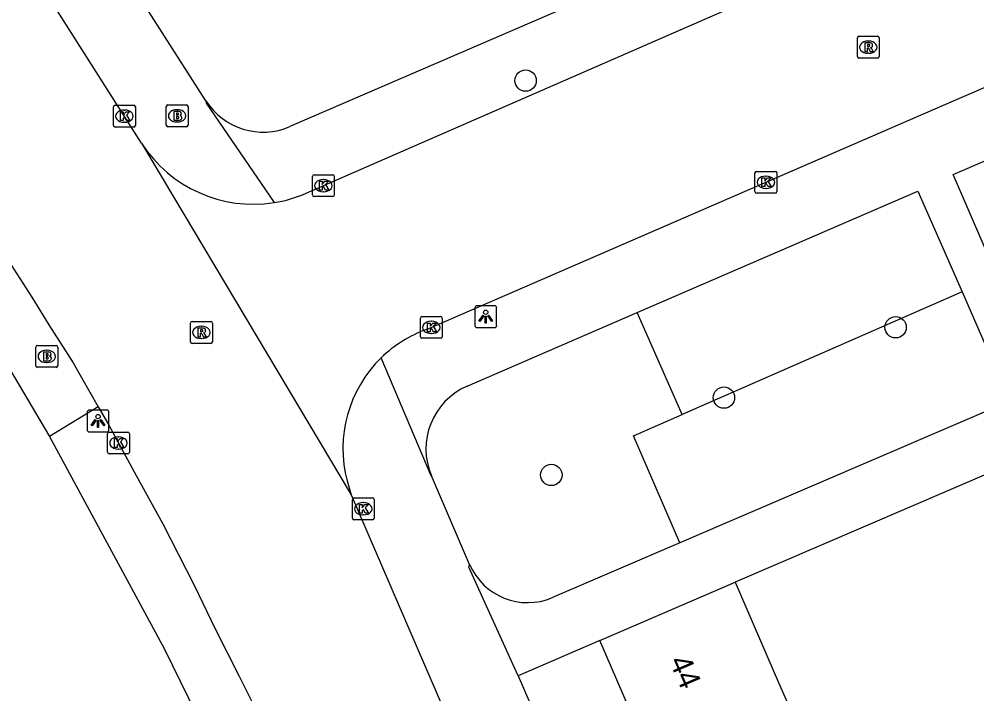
# Model space of a CAD drawing. Extents: x 159353 to 160616, y 385893 to 387321.
# Drawn here: x 159510 to 159553.81, y 386356.35 to 386387.21 of the extents above; entities that cross this region are included whole.
import ezdxf

# ---------------------------------------------------------------- set-up
doc = ezdxf.new("R2010")
doc.units = 0
for name, color, linetype in [('IMGEO_Boom', 7, 'Continuous'), ('IMGEO_Brandkraan', 7, 'Continuous'), ('IMGEO_Groenvoorziening', 7, 'Continuous'), ('IMGEO_Kolk', 7, 'Continuous'), ('IMGEO_Lichtpunt', 7, 'Continuous'), ('IMGEO_Muur', 7, 'Continuous'), ('IMGEO_Pand', 7, 'Continuous'), ('IMGEO_Pand_nummerreeks', 7, 'Continuous'), ('IMGEO_Rijbaan_lokaal_gesloten', 7, 'Continuous'), ('IMGEO_Rioolput', 7, 'Continuous'), ('IMGEO_Voetpad_open', 7, 'Continuous')]:
    doc.layers.add(name, color=color, linetype=linetype)

msp = doc.modelspace()

# ---------------------------------------------------------------- linework, layer by layer
at = {"layer": 'IMGEO_Boom'}
for centre in [(159533.167, 386384.407), (159550.091, 386373.12), (159542.239, 386369.903), (159534.343, 386366.368)]:
    msp.add_circle(centre, 0.489, dxfattribs=at)
at = {"layer": 'IMGEO_Brandkraan'}
for p, q in [((159516.802, 386383.292), (159517.654, 386383.292)), ((159516.727, 386382.366), (159516.727, 386383.218)), ((159517.215, 386383.072), (159517.24, 386383.072)), ((159517.728, 386383.218), (159517.728, 386382.366)), ((159517.238, 386382.512), (159517.213, 386382.512)), ((159517.654, 386382.292), (159516.802, 386382.292)), ((159510.839, 386372.289), (159511.691, 386372.289)), ((159510.764, 386371.363), (159510.764, 386372.215)), ((159511.252, 386372.069), (159511.277, 386372.069)), ((159511.765, 386372.215), (159511.765, 386371.363)), ((159511.275, 386371.509), (159511.25, 386371.509)), ((159511.691, 386371.289), (159510.839, 386371.289))]:
    msp.add_line(p, q, dxfattribs=at)
for points in [[(159516.802, 386383.292), (159517.654, 386383.292)], [(159516.727, 386382.366), (159516.727, 386383.218)], [(159517.075, 386382.992), (159517.075, 386382.592), (159517.288, 386382.592)], [(159517.306, 386382.992), (159517.075, 386382.992)], [(159517.254, 386382.911), (159517.2, 386382.911), (159517.2, 386382.835)], [(159517.2, 386382.835), (159517.253, 386382.835)], [(159517.728, 386383.218), (159517.728, 386382.366)], [(159517.262, 386382.759), (159517.2, 386382.759), (159517.2, 386382.678)], [(159517.2, 386382.678), (159517.262, 386382.678)], [(159517.654, 386382.292), (159516.802, 386382.292)], [(159510.839, 386372.289), (159511.691, 386372.289)], [(159510.764, 386371.363), (159510.764, 386372.215)], [(159511.112, 386371.989), (159511.112, 386371.589), (159511.325, 386371.589)], [(159511.343, 386371.989), (159511.112, 386371.989)], [(159511.291, 386371.908), (159511.237, 386371.908), (159511.237, 386371.832)], [(159511.765, 386372.215), (159511.765, 386371.363)], [(159511.237, 386371.832), (159511.29, 386371.832)], [(159511.299, 386371.756), (159511.237, 386371.756), (159511.237, 386371.675)], [(159511.237, 386371.675), (159511.299, 386371.675)], [(159511.691, 386371.289), (159510.839, 386371.289)]]:
    msp.add_lwpolyline(points, dxfattribs=at)
for centre, radius, start, end in [((159516.804, 386383.216), 0.0765, 91.552, 178.448), ((159516.804, 386383.216), 0.0765, 91.552, 178.448), ((159517.652, 386383.216), 0.0765, 1.552, 88.448), ((159517.652, 386383.216), 0.0765, 1.552, 88.448), ((159517.255, 386382.873), 0.0379, 267.8285, 90.9355), ((159517.31, 386382.847), 0.145, 59.4692, 91.5367), ((159517.335, 386382.894), 0.0922, 285.5137, 58.1501), ((159517.34, 386382.702), 0.105, 301.3115, 78.989), ((159516.804, 386382.368), 0.0765, 181.552, 268.448), ((159516.804, 386382.368), 0.0765, 181.552, 268.448), ((159517.263, 386382.718), 0.0404, 269.8759, 90.5077), ((159517.294, 386382.843), 0.251, 268.6676, 293.5347), ((159517.652, 386382.368), 0.0765, 271.552, 358.448), ((159517.652, 386382.368), 0.0765, 271.552, 358.448), ((159510.841, 386372.213), 0.0765, 91.552, 178.448), ((159510.841, 386372.213), 0.0765, 91.552, 178.448), ((159511.689, 386372.213), 0.0765, 1.552, 88.448), ((159511.689, 386372.213), 0.0765, 1.552, 88.448), ((159511.292, 386371.87), 0.0379, 267.8285, 90.9355), ((159511.347, 386371.844), 0.145, 59.4692, 91.5367), ((159511.372, 386371.891), 0.0922, 285.5137, 58.1501), ((159511.3, 386371.715), 0.0404, 269.8759, 90.5077), ((159511.331, 386371.84), 0.251, 268.6676, 293.5347), ((159511.377, 386371.699), 0.105, 301.3115, 78.989), ((159510.841, 386371.365), 0.0765, 181.552, 268.448), ((159510.841, 386371.365), 0.0765, 181.552, 268.448), ((159511.689, 386371.365), 0.0765, 271.552, 358.448), ((159511.689, 386371.365), 0.0765, 271.552, 358.448)]:
    msp.add_arc(centre, radius, start, end, dxfattribs=at)
for centre, major_axis, ratio, start_param, end_param in [((159517.214, 386382.792), (-0.387, 0.002), 0.722429, 4.712389, 7.853982), ((159517.239, 386382.792), (-0.39, 0.002), 0.717154, 1.570796, 4.712389), ((159511.251, 386371.789), (-0.387, 0.002), 0.722429, 4.712389, 7.853982), ((159511.276, 386371.789), (-0.39, 0.002), 0.717154, 1.570796, 4.712389)]:
    msp.add_ellipse(centre, major_axis=major_axis, ratio=ratio, start_param=start_param, end_param=end_param, dxfattribs=at)
at = {"layer": 'IMGEO_Groenvoorziening'}
for points in [[(159553.129, 386374.738), (159540.323, 386369.126)], [(159540.323, 386369.126), (159538.273, 386373.794)], [(159540.228, 386363.264), (159538.097, 386368.15), (159540.323, 386369.126)]]:
    msp.add_lwpolyline(points, dxfattribs=at)
at = {"layer": 'IMGEO_Kolk'}
for p, q in [((159514.39, 386383.277), (159515.242, 386383.277)), ((159514.315, 386382.351), (159514.315, 386383.203)), ((159514.803, 386383.057), (159514.828, 386383.057)), ((159515.316, 386383.203), (159515.316, 386382.351)), ((159514.826, 386382.497), (159514.801, 386382.497)), ((159515.242, 386382.277), (159514.39, 386382.277)), ((159543.659, 386379.327), (159543.659, 386380.179)), ((159543.734, 386380.253), (159544.586, 386380.253)), ((159544.66, 386380.179), (159544.66, 386379.327)), ((159523.417, 386379.173), (159523.417, 386380.025)), ((159523.492, 386380.099), (159524.344, 386380.099)), ((159523.905, 386379.879), (159523.93, 386379.879)), ((159524.418, 386380.025), (159524.418, 386379.173)), ((159544.147, 386380.033), (159544.172, 386380.033)), ((159523.928, 386379.319), (159523.903, 386379.319)), ((159544.17, 386379.473), (159544.145, 386379.473)), ((159524.344, 386379.099), (159523.492, 386379.099)), ((159544.586, 386379.253), (159543.734, 386379.253)), ((159528.427, 386373.616), (159529.279, 386373.616)), ((159528.352, 386372.69), (159528.352, 386373.542)), ((159528.84, 386373.396), (159528.865, 386373.396)), ((159529.353, 386373.542), (159529.353, 386372.69)), ((159528.863, 386372.836), (159528.838, 386372.836)), ((159529.279, 386372.616), (159528.427, 386372.616)), ((159514.043, 386367.402), (159514.043, 386368.254)), ((159514.118, 386368.328), (159514.97, 386368.328)), ((159514.531, 386368.108), (159514.556, 386368.108)), ((159515.044, 386368.254), (159515.044, 386367.402)), ((159514.554, 386367.548), (159514.529, 386367.548)), ((159514.97, 386367.328), (159514.118, 386367.328)), ((159525.317, 386365.321), (159526.169, 386365.321)), ((159525.242, 386364.395), (159525.242, 386365.247)), ((159525.73, 386365.101), (159525.755, 386365.101)), ((159526.243, 386365.247), (159526.243, 386364.395)), ((159525.753, 386364.541), (159525.728, 386364.541)), ((159526.169, 386364.321), (159525.317, 386364.321))]:
    msp.add_line(p, q, dxfattribs=at)
for points in [[(159514.39, 386383.277), (159515.242, 386383.277)], [(159514.315, 386382.351), (159514.315, 386383.203)], [(159514.636, 386382.977), (159514.759, 386382.977), (159514.759, 386382.826), (159514.889, 386382.977), (159515.053, 386382.977), (159514.907, 386382.826), (159515.06, 386382.577), (159514.908, 386382.577), (159514.823, 386382.741), (159514.759, 386382.674), (159514.759, 386382.577), (159514.636, 386382.577), (159514.636, 386382.977)], [(159515.316, 386383.203), (159515.316, 386382.351)], [(159515.242, 386382.277), (159514.39, 386382.277)], [(159543.659, 386379.327), (159543.659, 386380.179)], [(159543.734, 386380.253), (159544.586, 386380.253)], [(159544.66, 386380.179), (159544.66, 386379.327)], [(159523.417, 386379.173), (159523.417, 386380.025)], [(159523.492, 386380.099), (159524.344, 386380.099)], [(159523.738, 386379.799), (159523.861, 386379.799), (159523.861, 386379.648), (159523.991, 386379.799), (159524.155, 386379.799), (159524.009, 386379.648), (159524.162, 386379.399), (159524.01, 386379.399), (159523.925, 386379.563), (159523.861, 386379.496), (159523.861, 386379.399), (159523.738, 386379.399), (159523.738, 386379.799)], [(159524.418, 386380.025), (159524.418, 386379.173)], [(159543.98, 386379.953), (159544.103, 386379.953), (159544.103, 386379.802), (159544.233, 386379.953), (159544.397, 386379.953), (159544.251, 386379.802), (159544.404, 386379.553), (159544.252, 386379.553), (159544.167, 386379.717), (159544.103, 386379.65), (159544.103, 386379.553), (159543.98, 386379.553), (159543.98, 386379.953)], [(159524.344, 386379.099), (159523.492, 386379.099)], [(159544.586, 386379.253), (159543.734, 386379.253)], [(159528.427, 386373.616), (159529.279, 386373.616)], [(159528.352, 386372.69), (159528.352, 386373.542)], [(159528.673, 386373.316), (159528.796, 386373.316), (159528.796, 386373.165), (159528.926, 386373.316), (159529.09, 386373.316), (159528.944, 386373.165), (159529.097, 386372.916), (159528.945, 386372.916), (159528.86, 386373.08), (159528.796, 386373.013), (159528.796, 386372.916), (159528.673, 386372.916), (159528.673, 386373.316)], [(159529.353, 386373.542), (159529.353, 386372.69)], [(159529.279, 386372.616), (159528.427, 386372.616)], [(159514.043, 386367.402), (159514.043, 386368.254)], [(159514.118, 386368.328), (159514.97, 386368.328)], [(159514.364, 386368.028), (159514.487, 386368.028), (159514.487, 386367.877), (159514.617, 386368.028), (159514.781, 386368.028), (159514.635, 386367.877), (159514.788, 386367.628), (159514.636, 386367.628), (159514.551, 386367.792), (159514.487, 386367.725), (159514.487, 386367.628), (159514.364, 386367.628), (159514.364, 386368.028)], [(159515.044, 386368.254), (159515.044, 386367.402)], [(159514.97, 386367.328), (159514.118, 386367.328)], [(159525.317, 386365.321), (159526.169, 386365.321)], [(159525.242, 386364.395), (159525.242, 386365.247)], [(159525.563, 386365.021), (159525.686, 386365.021), (159525.686, 386364.87), (159525.816, 386365.021), (159525.98, 386365.021), (159525.834, 386364.87), (159525.987, 386364.621), (159525.835, 386364.621), (159525.75, 386364.785), (159525.686, 386364.718), (159525.686, 386364.621), (159525.563, 386364.621), (159525.563, 386365.021)], [(159526.243, 386365.247), (159526.243, 386364.395)], [(159526.169, 386364.321), (159525.317, 386364.321)]]:
    msp.add_lwpolyline(points, dxfattribs=at)
for centre, start, end in [((159514.392, 386383.201), 91.552, 178.448), ((159514.392, 386383.201), 91.552, 178.448), ((159515.24, 386383.201), 1.552, 88.448), ((159515.24, 386383.201), 1.552, 88.448), ((159514.392, 386382.353), 181.552, 268.448), ((159514.392, 386382.353), 181.552, 268.448), ((159515.24, 386382.353), 271.552, 358.448), ((159515.24, 386382.353), 271.552, 358.448), ((159543.736, 386380.177), 91.552, 178.448), ((159543.736, 386380.177), 91.552, 178.448), ((159544.584, 386380.177), 1.552, 88.448), ((159544.584, 386380.177), 1.552, 88.448), ((159523.494, 386380.023), 91.552, 178.448), ((159523.494, 386380.023), 91.552, 178.448), ((159524.342, 386380.023), 1.552, 88.448), ((159524.342, 386380.023), 1.552, 88.448), ((159543.736, 386379.329), 181.552, 268.448), ((159543.736, 386379.329), 181.552, 268.448), ((159544.584, 386379.329), 271.552, 358.448), ((159544.584, 386379.329), 271.552, 358.448), ((159523.494, 386379.175), 181.552, 268.448), ((159523.494, 386379.175), 181.552, 268.448), ((159524.342, 386379.175), 271.552, 358.448), ((159524.342, 386379.175), 271.552, 358.448), ((159528.429, 386373.54), 91.552, 178.448), ((159528.429, 386373.54), 91.552, 178.448), ((159529.277, 386373.54), 1.552, 88.448), ((159529.277, 386373.54), 1.552, 88.448), ((159528.429, 386372.692), 181.552, 268.448), ((159528.429, 386372.692), 181.552, 268.448), ((159529.277, 386372.692), 271.552, 358.448), ((159529.277, 386372.692), 271.552, 358.448), ((159514.12, 386368.252), 91.552, 178.448), ((159514.12, 386368.252), 91.552, 178.448), ((159514.968, 386368.252), 1.552, 88.448), ((159514.968, 386368.252), 1.552, 88.448), ((159514.12, 386367.404), 181.552, 268.448), ((159514.12, 386367.404), 181.552, 268.448), ((159514.968, 386367.404), 271.552, 358.448), ((159514.968, 386367.404), 271.552, 358.448), ((159525.319, 386365.245), 91.552, 178.448), ((159525.319, 386365.245), 91.552, 178.448), ((159526.167, 386365.245), 1.552, 88.448), ((159526.167, 386365.245), 1.552, 88.448), ((159525.319, 386364.397), 181.552, 268.448), ((159525.319, 386364.397), 181.552, 268.448), ((159526.167, 386364.397), 271.552, 358.448), ((159526.167, 386364.397), 271.552, 358.448)]:
    msp.add_arc(centre, 0.0765, start, end, dxfattribs=at)
for centre, major_axis, ratio, start_param, end_param in [((159514.802, 386382.777), (-0.387, 0.002), 0.722429, 4.712389, 7.853982), ((159514.827, 386382.777), (-0.39, 0.002), 0.717154, 1.570796, 4.712389), ((159523.904, 386379.599), (-0.387, 0.002), 0.722429, 4.712389, 7.853982), ((159523.929, 386379.599), (-0.39, 0.002), 0.717154, 1.570796, 4.712389), ((159544.146, 386379.753), (-0.387, 0.002), 0.722429, 4.712389, 7.853982), ((159544.171, 386379.753), (-0.39, 0.002), 0.717154, 1.570796, 4.712389), ((159528.839, 386373.116), (-0.387, 0.002), 0.722429, 4.712389, 7.853982), ((159528.864, 386373.116), (-0.39, 0.002), 0.717154, 1.570796, 4.712389), ((159514.53, 386367.828), (-0.387, 0.002), 0.722429, 4.712389, 7.853982), ((159514.555, 386367.828), (-0.39, 0.002), 0.717154, 1.570796, 4.712389), ((159525.729, 386364.821), (-0.387, 0.002), 0.722429, 4.712389, 7.853982), ((159525.754, 386364.821), (-0.39, 0.002), 0.717154, 1.570796, 4.712389)]:
    msp.add_ellipse(centre, major_axis=major_axis, ratio=ratio, start_param=start_param, end_param=end_param, dxfattribs=at)
at = {"layer": 'IMGEO_Lichtpunt'}
for p, q in [((159531.749, 386374.103), (159530.941, 386374.103)), ((159531.749, 386374.103), (159530.941, 386374.103)), ((159530.847, 386374.008), (159530.847, 386373.201)), ((159530.847, 386374.008), (159530.847, 386373.201)), ((159531.843, 386373.201), (159531.843, 386374.008)), ((159531.843, 386373.201), (159531.843, 386374.008)), ((159530.941, 386373.107), (159531.749, 386373.107)), ((159530.941, 386373.107), (159531.749, 386373.107)), ((159513.112, 386369.239), (159513.112, 386368.432)), ((159513.112, 386369.239), (159513.112, 386368.432)), ((159514.014, 386369.334), (159513.206, 386369.334)), ((159514.014, 386369.334), (159513.206, 386369.334)), ((159514.108, 386368.432), (159514.108, 386369.239)), ((159514.108, 386368.432), (159514.108, 386369.239)), ((159513.206, 386368.338), (159514.014, 386368.338)), ((159513.206, 386368.338), (159514.014, 386368.338))]:
    msp.add_line(p, q, dxfattribs=at)
for points in [[(159531.221, 386373.672), (159531.26, 386373.644), (159531.072, 386373.382), (159531.034, 386373.409), (159531.221, 386373.672)], [(159531.323, 386373.624), (159531.37, 386373.624), (159531.37, 386373.302), (159531.323, 386373.302), (159531.323, 386373.624)], [(159531.433, 386373.644), (159531.471, 386373.671), (159531.658, 386373.409), (159531.619, 386373.381), (159531.433, 386373.644)], [(159513.486, 386368.903), (159513.525, 386368.875), (159513.337, 386368.613), (159513.299, 386368.64), (159513.486, 386368.903)], [(159513.588, 386368.855), (159513.635, 386368.855), (159513.635, 386368.533), (159513.588, 386368.533), (159513.588, 386368.855)], [(159513.698, 386368.875), (159513.736, 386368.902), (159513.923, 386368.64), (159513.884, 386368.612), (159513.698, 386368.875)]]:
    msp.add_lwpolyline(points, dxfattribs=at)
for centre in [(159531.346, 386373.806), (159513.611, 386369.037)]:
    msp.add_circle(centre, 0.0994, dxfattribs=at)
for centre, start, end in [((159530.941, 386374.008), 90, 180), ((159530.941, 386374.008), 90, 180), ((159531.749, 386374.008), 0, 90), ((159531.749, 386374.008), 0, 90), ((159530.941, 386373.201), 180, 270), ((159530.941, 386373.201), 180, 270), ((159531.749, 386373.201), 270, 0), ((159531.749, 386373.201), 270, 360), ((159513.206, 386369.239), 90, 180), ((159513.206, 386369.239), 90, 180), ((159514.014, 386369.239), 0, 90), ((159514.014, 386369.239), 0, 90), ((159513.206, 386368.432), 180, 270), ((159513.206, 386368.432), 180, 270), ((159514.014, 386368.432), 270, 0), ((159514.014, 386368.432), 270, 360)]:
    msp.add_arc(centre, 0.0946, start, end, dxfattribs=at)
at = {"layer": 'IMGEO_Muur'}
msp.add_lwpolyline([(159556.517, 386367.373), (159542.759, 386361.47)], dxfattribs=at)
at = {"layer": 'IMGEO_Pand'}
for points in [[(159536.57, 386358.8), (159542.759, 386361.47)], [(159542.759, 386361.47), (159544.739, 386356.879), (159545.132, 386355.967)], [(159538.943, 386353.297), (159536.57, 386358.8)]]:
    msp.add_lwpolyline(points, dxfattribs=at)
at = {"layer": 'IMGEO_Rijbaan_lokaal_gesloten'}
for points in [[(159515.604, 386381.536), (159500.36, 386405.492), (159500, 386406.055), (159471.301, 386450.928)], [(159523.135, 386379.256), (159544.96, 386388.795), (159556.875, 386393.929), (159564.458, 386397.238)], [(159528.635, 386373.023), (159553.089, 386383.626), (159573.819, 386392.563)], [(159515.604, 386381.536), (159525.194, 386365.458)], [(159508.049, 386378.563), (159509.479, 386376.213), (159510.58, 386374.496), (159511.352, 386373.226), (159512.473, 386371.498), (159513.621, 386369.485)], [(159513.621, 386369.485), (159514.085, 386368.672), (159515.356, 386366.345), (159516.578, 386364.138), (159518, 386361.321), (159518.981, 386359.293), (159520.063, 386357.166), (159521.044, 386355.208), (159522.497, 386352.051), (159523.869, 386348.954), (159528.006, 386339.414), (159538.567, 386315.088)], [(159525.008, 386366.09), (159525.194, 386365.458)], [(159525.194, 386365.458), (159527.379, 386360.366), (159547.269, 386314.331)]]:
    msp.add_lwpolyline(points, dxfattribs=at)
for centre, radius, start, end in [((159520.708, 386384.815), 6.066, 212.7203, 279.0321), ((159520.707, 386384.812), 6.063, 279.0425, 293.6062), ((159530.607, 386367.573), 5.796, 109.8888, 134.2708), ((159530.607, 386367.577), 5.793, 134.2981, 194.8752)]:
    msp.add_arc(centre, radius, start, end, dxfattribs=at)
at = {"layer": 'IMGEO_Rioolput'}
for p, q in [((159548.342, 386385.506), (159548.342, 386386.358)), ((159548.417, 386386.432), (159549.269, 386386.432)), ((159549.343, 386386.358), (159549.343, 386385.506)), ((159548.83, 386386.212), (159548.855, 386386.212)), ((159549.269, 386385.432), (159548.417, 386385.432)), ((159548.853, 386385.652), (159548.828, 386385.652)), ((159517.837, 386372.46), (159517.837, 386373.312)), ((159517.912, 386373.386), (159518.764, 386373.386)), ((159518.325, 386373.166), (159518.35, 386373.166)), ((159518.838, 386373.312), (159518.838, 386372.46)), ((159518.764, 386372.386), (159517.912, 386372.386)), ((159518.348, 386372.606), (159518.323, 386372.606))]:
    msp.add_line(p, q, dxfattribs=at)
for points in [[(159548.342, 386385.506), (159548.342, 386386.358)], [(159548.417, 386386.432), (159549.269, 386386.432)], [(159549.343, 386386.358), (159549.343, 386385.506)], [(159548.931, 386386.13), (159548.679, 386386.132), (159548.679, 386385.732)], [(159548.679, 386385.732), (159548.803, 386385.732), (159548.803, 386385.894), (159548.814, 386385.894)], [(159548.857, 386386.051), (159548.803, 386386.051), (159548.803, 386385.97)], [(159548.803, 386385.97), (159548.855, 386385.97)], [(159548.861, 386385.865), (159548.932, 386385.732), (159549.072, 386385.732), (159549.007, 386385.858)], [(159549.269, 386385.432), (159548.417, 386385.432)], [(159517.837, 386372.46), (159517.837, 386373.312)], [(159517.912, 386373.386), (159518.764, 386373.386)], [(159518.838, 386373.312), (159518.838, 386372.46)], [(159518.426, 386373.084), (159518.174, 386373.086), (159518.174, 386372.686)], [(159518.174, 386372.686), (159518.298, 386372.686), (159518.298, 386372.848), (159518.309, 386372.848)], [(159518.352, 386373.005), (159518.298, 386373.005), (159518.298, 386372.924)], [(159518.298, 386372.924), (159518.35, 386372.924)], [(159518.356, 386372.819), (159518.427, 386372.686), (159518.567, 386372.686), (159518.502, 386372.812)], [(159518.764, 386372.386), (159517.912, 386372.386)]]:
    msp.add_lwpolyline(points, dxfattribs=at)
for centre, radius, start, end in [((159548.419, 386386.356), 0.0765, 91.552, 178.448), ((159548.419, 386386.356), 0.0765, 91.552, 178.448), ((159549.267, 386386.356), 0.0765, 1.552, 88.448), ((159549.267, 386386.356), 0.0765, 1.552, 88.448), ((159548.813, 386385.841), 0.0533, 26.0293, 88.6989), ((159548.839, 386386.159), 0.19, 274.7715, 282.9687), ((159548.863, 386385.955), 0.0964, 77.0061, 93.1865), ((159548.877, 386386.012), 0.0378, 276.6634, 79.6772), ((159548.93, 386386.02), 0.109, 350.3612, 89.416), ((159548.928, 386386.02), 0.112, 277.5842, 350.9817), ((159548.912, 386385.805), 0.108, 29.5134, 73.7905), ((159548.419, 386385.508), 0.0765, 181.552, 268.448), ((159548.419, 386385.508), 0.0765, 181.552, 268.448), ((159549.267, 386385.508), 0.0765, 271.552, 358.448), ((159549.267, 386385.508), 0.0765, 271.552, 358.448), ((159517.914, 386373.31), 0.0765, 91.552, 178.448), ((159517.914, 386373.31), 0.0765, 91.552, 178.448), ((159518.762, 386373.31), 0.0765, 1.552, 88.448), ((159518.762, 386373.31), 0.0765, 1.552, 88.448), ((159518.308, 386372.795), 0.0533, 26.0293, 88.6989), ((159518.334, 386373.113), 0.19, 274.7715, 282.9687), ((159518.358, 386372.909), 0.0964, 77.0061, 93.1865), ((159518.372, 386372.966), 0.0378, 276.6634, 79.6772), ((159518.425, 386372.974), 0.109, 350.3612, 89.416), ((159518.423, 386372.974), 0.112, 277.5842, 350.9817), ((159518.407, 386372.759), 0.108, 29.5134, 73.7905), ((159517.914, 386372.462), 0.0765, 181.552, 268.448), ((159517.914, 386372.462), 0.0765, 181.552, 268.448), ((159518.762, 386372.462), 0.0765, 271.552, 358.448), ((159518.762, 386372.462), 0.0765, 271.552, 358.448)]:
    msp.add_arc(centre, radius, start, end, dxfattribs=at)
for centre, major_axis, ratio, start_param, end_param in [((159548.829, 386385.932), (-0.387, 0.002), 0.722429, 4.712389, 7.853982), ((159548.854, 386385.932), (-0.39, 0.002), 0.717154, 1.570796, 4.712389), ((159518.324, 386372.886), (-0.387, 0.002), 0.722429, 4.712389, 7.853982), ((159518.349, 386372.886), (-0.39, 0.002), 0.717154, 1.570796, 4.712389)]:
    msp.add_ellipse(centre, major_axis=major_axis, ratio=ratio, start_param=start_param, end_param=end_param, dxfattribs=at)
at = {"layer": 'IMGEO_Voetpad_open'}
for points in [[(159518.546, 386383.479), (159500, 386412.48), (159489.886, 386428.296)], [(159541.974, 386390.773), (159522.39, 386382.298)], [(159554.779, 386375.346), (159552.719, 386380.111), (159566.026, 386385.827)], [(159518.546, 386383.479), (159518.558, 386383.368), (159521.66, 386378.824)], [(159538.273, 386373.794), (159551.112, 386379.348), (159553.129, 386374.738)], [(159506.211, 386376.719), (159507.312, 386374.992), (159511.384, 386368.121)], [(159553.129, 386374.738), (159555.313, 386369.747), (159540.228, 386363.264)], [(159530.49, 386370.427), (159538.273, 386373.794)], [(159528.864, 386366.324), (159528.854, 386366.326), (159526.561, 386371.723)], [(159513.621, 386369.485), (159511.384, 386368.121)], [(159511.384, 386368.121), (159516.654, 386358.401), (159519.208, 386353.167), (159536.89, 386312.44)], [(159556.517, 386367.373), (159542.759, 386361.47)], [(159530.608, 386362.272), (159528.864, 386366.324)], [(159540.228, 386363.264), (159534.401, 386360.76)], [(159532.833, 386357.179), (159530.576, 386362.156), (159530.608, 386362.272)], [(159536.57, 386358.8), (159532.833, 386357.179)], [(159532.833, 386357.179), (159552.875, 386310.756)]]:
    msp.add_lwpolyline(points, dxfattribs=at)
for centre, radius, start, end in [((159521.165, 386385.159), 3.112, 212.6676, 293.1751), ((159531.734, 386367.56), 3.125, 113.4585, 203.3051), ((159533.261, 386363.414), 2.888, 203.2848, 293.2479)]:
    msp.add_arc(centre, radius, start, end, dxfattribs=at)

# ---------------------------------------------------------------- texts
at = {"layer": 'IMGEO_Pand_nummerreeks'}
msp.add_text('44', height=1, rotation=293.3248, dxfattribs=at).set_placement((159539.721, 386357.857))

doc.saveas('drawing.dxf')
